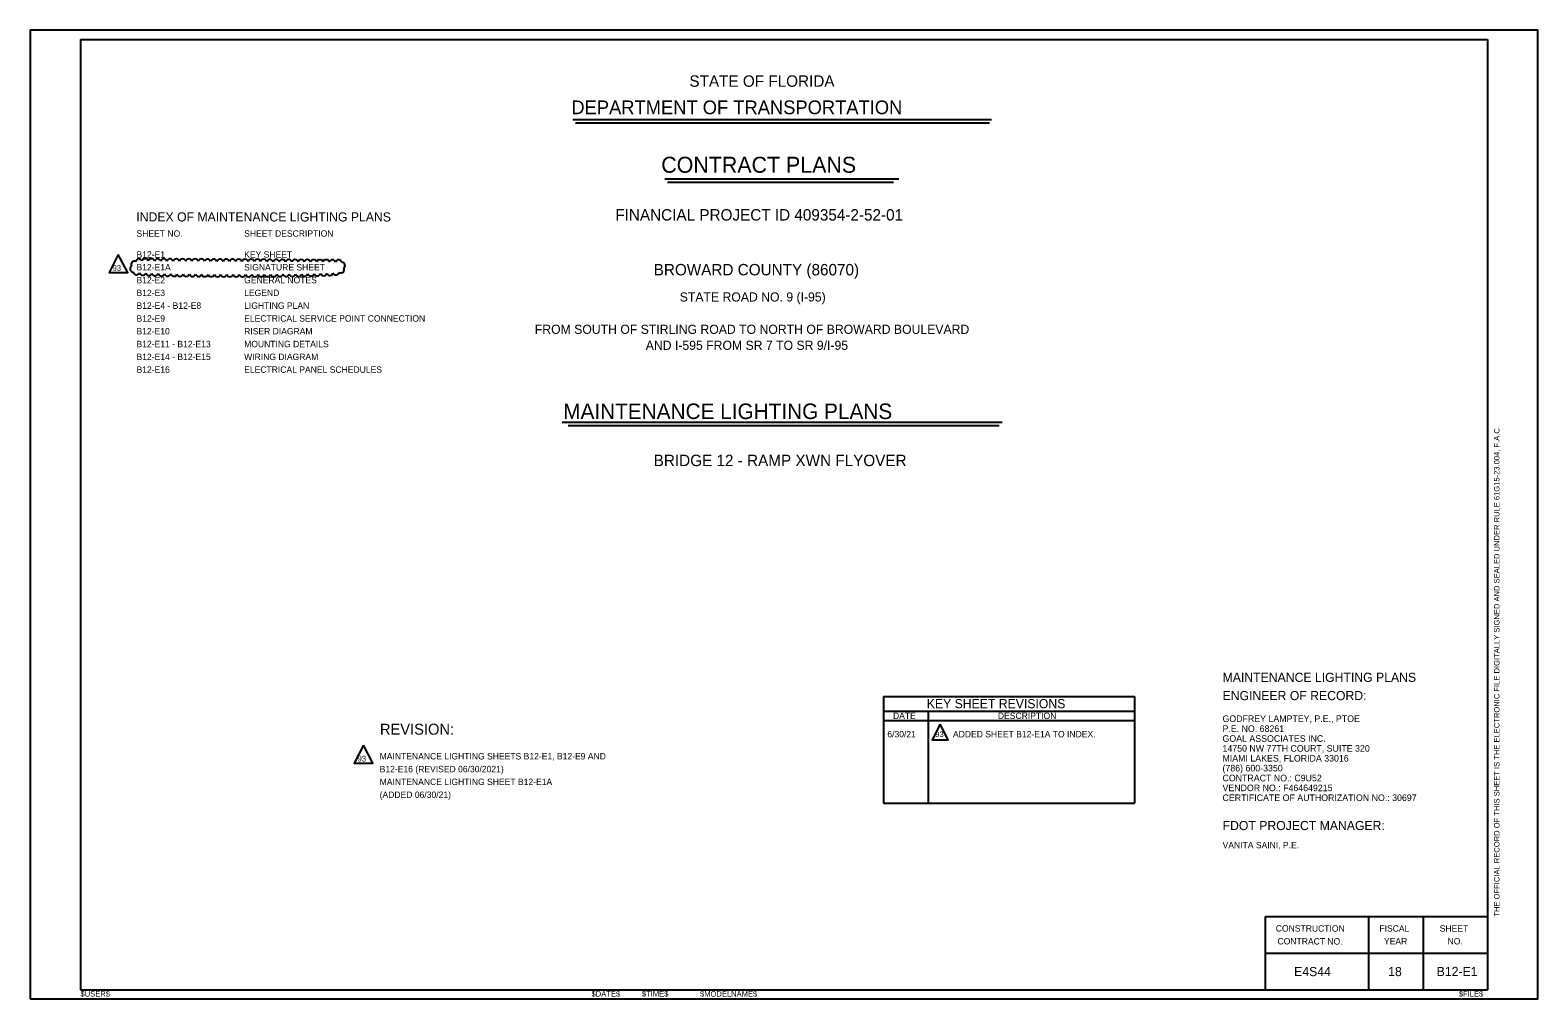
# Model space of a CAD drawing. Extents: x -820.2 to -803.7, y -2199.1 to -2188.5.
import ezdxf

# ---------------------------------------------------------------- set-up
doc = ezdxf.new("R2010")
doc.units = 0
for name, color, linetype in [('ActivePointCell_dp', 7, 'Continuous'), ('AdhocPoint_dp', 7, 'Continuous'), ('Cloud_dp', 7, 'Continuous'), ('PlotBorder_dp', 7, 'Continuous'), ('SheetBorder_dp', 7, 'Continuous'), ('SheetLines_dp', 7, 'Continuous'), ('SumBoxLines_dp', 7, 'Continuous'), ('TextLabel', 7, 'Continuous'), ('TextMinor', 7, 'Continuous'), ('TextMisc', 7, 'Continuous'), ('TextNotes', 7, 'Continuous'), ('TextTitle', 7, 'Continuous')]:
    doc.layers.add(name, color=color, linetype=linetype)

msp = doc.modelspace()

# ---------------------------------------------------------------- linework, layer by layer
at = {"layer": 'ActivePointCell_dp'}
msp.add_line((-804.277, -2188.624), (-804.277, -2188.624), dxfattribs=at)
at = {"layer": 'AdhocPoint_dp'}
msp.add_line((-803.727, -2199.124), (-803.727, -2199.124), dxfattribs=at)
at = {"layer": 'Cloud_dp'}
for points in [[(-819.262, -2190.977), (-819.364, -2191.174), (-819.159, -2191.174)], [(-810.268, -2196.119), (-810.356, -2196.288), (-810.18, -2196.288)]]:
    msp.add_lwpolyline(points, close=True, dxfattribs=at)
for centre, start, end in [((-819.036, -2191.063), 23.0939, 168.0939), ((-818.969, -2191.06), 17.1666, 162.1666), ((-818.901, -2191.06), 17.1666, 162.1666), ((-818.832, -2191.061), 17.1666, 162.1666), ((-818.764, -2191.061), 17.1666, 162.1666), ((-818.696, -2191.061), 17.1666, 162.1666), ((-818.627, -2191.062), 17.1666, 162.1666), ((-818.559, -2191.062), 17.1666, 162.1666), ((-818.491, -2191.063), 17.1666, 162.1666), ((-818.422, -2191.063), 17.1666, 162.1666), ((-818.354, -2191.063), 17.1666, 162.1666), ((-818.286, -2191.064), 17.1666, 162.1666), ((-818.217, -2191.064), 17.1666, 162.1666), ((-818.149, -2191.065), 17.1666, 162.1666), ((-818.081, -2191.065), 17.1666, 162.1666), ((-818.012, -2191.065), 17.1666, 162.1666), ((-817.944, -2191.066), 17.1667, 162.1667), ((-817.876, -2191.066), 17.1673, 162.1673), ((-817.808, -2191.067), 17.1678, 162.1678), ((-817.739, -2191.067), 17.1685, 162.1685), ((-817.671, -2191.067), 17.1692, 162.1692), ((-817.603, -2191.068), 17.17, 162.17), ((-817.534, -2191.068), 17.1709, 162.1709), ((-817.466, -2191.069), 17.172, 162.172), ((-817.398, -2191.069), 17.1733, 162.1733), ((-817.329, -2191.069), 17.1748, 162.1748), ((-817.261, -2191.07), 17.1767, 162.1767), ((-817.193, -2191.07), 17.1791, 162.1791), ((-817.124, -2191.071), 17.1823, 162.1823), ((-819.098, -2191.134), 124.4418, 269.4418), ((-819.087, -2191.088), 63.3859, 208.3859), ((-819.063, -2191.164), 190.134, 335.134), ((-818.996, -2191.17), 193.8651, 338.8651), ((-818.928, -2191.174), 194.9982, 339.9982), ((-818.86, -2191.176), 195.6143, 340.6143), ((-818.792, -2191.178), 196.0167, 341.0167), ((-818.723, -2191.18), 196.3062, 341.3062), ((-818.655, -2191.181), 196.5273, 341.5273), ((-818.587, -2191.182), 196.7034, 341.7034), ((-818.519, -2191.183), 196.8479, 341.8479), ((-818.45, -2191.184), 196.9693, 341.9693), ((-818.382, -2191.184), 197.0731, 342.0731), ((-818.314, -2191.185), 197.1633, 342.1633), ((-818.245, -2191.185), 197.2425, 342.2425), ((-818.177, -2191.186), 197.3128, 342.3128), ((-818.109, -2191.186), 197.3758, 342.3758), ((-818.041, -2191.186), 197.4327, 342.4327), ((-817.972, -2191.186), 197.4844, 342.4844), ((-817.904, -2191.186), 197.5356, 342.5356), ((-817.836, -2191.186), 197.5918, 342.5918), ((-817.767, -2191.186), 197.6538, 342.6538), ((-817.699, -2191.185), 197.7228, 342.7228), ((-817.631, -2191.185), 197.8002, 342.8002), ((-817.562, -2191.185), 197.8878, 342.8878), ((-817.494, -2191.184), 197.9881, 342.9881), ((-817.426, -2191.184), 198.1044, 343.1044), ((-817.358, -2191.183), 198.2416, 343.2416), ((-817.289, -2191.182), 198.4068, 343.4068), ((-817.221, -2191.181), 198.611, 343.611), ((-817.153, -2191.179), 198.8725, 343.8725), ((-817.085, -2191.177), 199.2244, 344.2244), ((-817.056, -2191.071), 17.187, 162.187), ((-817.016, -2191.175), 199.7353, 344.7353), ((-816.988, -2191.071), 17.1948, 162.1948), ((-816.948, -2191.172), 200.5799, 345.5799), ((-816.919, -2191.072), 17.2118, 162.2118), ((-816.88, -2191.167), 202.4501, 347.4501), ((-816.852, -2191.073), 14.8094, 159.8094), ((-816.827, -2191.144), 239.6728, 24.6728), ((-816.816, -2191.1), 306.3283, 91.3283)]:
    msp.add_arc(centre, 0.0358, start, end, dxfattribs=at)
at = {"layer": 'PlotBorder_dp'}
msp.add_lwpolyline([(-820.227, -2199.124), (-803.727, -2199.124), (-803.727, -2188.524), (-820.227, -2188.524)], close=True, dxfattribs=at)
at = {"layer": 'SheetBorder_dp'}
for p, q in [((-819.677, -2188.624), (-819.677, -2199.024)), ((-819.677, -2188.624), (-804.277, -2188.624)), ((-804.277, -2188.624), (-804.277, -2199.024)), ((-819.677, -2199.024), (-804.277, -2199.024))]:
    msp.add_line(p, q, dxfattribs=at)
at = {"layer": 'SheetLines_dp'}
for p, q in [((-806.708, -2198.224), (-804.277, -2198.224)), ((-806.708, -2199.024), (-806.708, -2198.224)), ((-805.577, -2199.024), (-805.577, -2198.224)), ((-804.977, -2199.024), (-804.977, -2198.224)), ((-806.708, -2198.624), (-804.277, -2198.624))]:
    msp.add_line(p, q, dxfattribs=at)
at = {"layer": 'SumBoxLines_dp'}
for p, q in [((-810.888, -2195.816), (-810.888, -2196.984)), ((-810.888, -2195.816), (-808.141, -2195.816)), ((-808.141, -2195.816), (-808.141, -2196.984)), ((-810.888, -2195.976), (-808.141, -2195.976)), ((-810.398, -2195.976), (-810.398, -2196.984)), ((-810.888, -2196.076), (-808.141, -2196.076)), ((-810.888, -2196.984), (-808.141, -2196.984))]:
    msp.add_line(p, q, dxfattribs=at)
at = {"layer": 'TextNotes'}
msp.add_lwpolyline([(-816.579, -2196.346), (-816.681, -2196.543), (-816.476, -2196.543)], close=True, dxfattribs=at)
at = {"layer": 'TextTitle'}
for p, q in [((-814.289, -2189.5), (-809.707, -2189.5)), ((-814.257, -2189.538), (-809.729, -2189.538)), ((-813.281, -2190.15), (-810.719, -2190.15)), ((-813.253, -2190.188), (-810.777, -2190.188)), ((-814.404, -2192.813), (-809.59, -2192.813)), ((-814.339, -2192.851), (-809.624, -2192.851))]:
    msp.add_line(p, q, dxfattribs=at)

# ---------------------------------------------------------------- texts
at = {"layer": 'Cloud_dp'}
for height, p in [(0.0622, (-819.325, -2191.157)), (0.06, (-810.322, -2196.258))]:
    msp.add_text('93', height=height, rotation=0, dxfattribs=at).set_placement(p)
at = {"layer": 'TextLabel'}
for s, height, p in [('INDEX OF MAINTENANCE LIGHTING PLANS', 0.1, (-819.065, -2190.617)), ('FINANCIAL PROJECT ID 409354-2-52-01', 0.125, (-813.823, -2190.607)), ('B12-E1', 0.07, (-819.063, -2191.013)), ('KEY SHEET', 0.07, (-817.885, -2191.013)), ('B12-E1A', 0.07, (-819.063, -2191.153)), ('SIGNATURE SHEET', 0.07, (-817.885, -2191.153)), ('BROWARD COUNTY (86070)', 0.125, (-813.403, -2191.207)), ('B12-E2', 0.07, (-819.063, -2191.293)), ('B12-E3', 0.07, (-819.063, -2191.433)), ('GENERAL NOTES', 0.07, (-817.885, -2191.293)), ('LEGEND', 0.07, (-817.885, -2191.433)), ('B12-E4 - B12-E8', 0.07, (-819.063, -2191.573)), ('LIGHTING PLAN', 0.07, (-817.885, -2191.573)), ('STATE ROAD NO. 9 (I-95)', 0.1, (-813.118, -2191.493)), ('B12-E9', 0.07, (-819.063, -2191.713)), ('ELECTRICAL SERVICE POINT CONNECTION', 0.07, (-817.885, -2191.713)), ('B12-E10', 0.07, (-819.063, -2191.853)), ('RISER DIAGRAM', 0.07, (-817.885, -2191.853)), ('FROM SOUTH OF STIRLING ROAD TO NORTH OF BROWARD BOULEVARD', 0.1, (-814.704, -2191.847)), ('B12-E11 - B12-E13', 0.07, (-819.063, -2191.993)), ('MOUNTING DETAILS', 0.07, (-817.885, -2191.993)), ('AND I-595 FROM SR 7 TO SR 9/I-95', 0.1, (-813.49, -2192.022)), ('B12-E14 - B12-E15', 0.07, (-819.063, -2192.133)), ('WIRING DIAGRAM', 0.07, (-817.885, -2192.133)), ('B12-E16', 0.07, (-819.063, -2192.273)), ('ELECTRICAL PANEL SCHEDULES', 0.07, (-817.885, -2192.273)), ('BRIDGE 12 - RAMP XWN FLYOVER', 0.125, (-813.403, -2193.294)), ('MAINTENANCE LIGHTING PLANS', 0.1, (-807.177, -2195.655)), ('ENGINEER OF RECORD:', 0.1, (-807.177, -2195.855)), ('KEY SHEET REVISIONS', 0.1, (-810.414, -2195.943)), ('REVISION:', 0.12, (-816.399, -2196.233)), ('GODFREY LAMPTEY, P.E., PTOE', 0.07202, (-807.178, -2196.094)), ('P.E. NO. 68261', 0.07202, (-807.178, -2196.203)), ('GOAL ASSOCIATES INC. ', 0.07202, (-807.178, -2196.311)), ('14750 NW 77TH COURT, SUITE 320', 0.07202, (-807.178, -2196.419)), ('MIAMI LAKES, FLORIDA 33016', 0.07202, (-807.178, -2196.527)), ('(786) 600-3350', 0.07202, (-807.178, -2196.635)), ('VENDOR NO.: F464649215', 0.07202, (-807.178, -2196.851)), ('CONTRACT NO.: C9U52', 0.07202, (-807.178, -2196.743)), ('CERTIFICATE OF AUTHORIZATION NO.: 30697', 0.07202, (-807.178, -2196.959)), ('E4S44', 0.1, (-806.394, -2198.875)), ('18', 0.1, (-805.365, -2198.875)), ('B12-E1', 0.1, (-804.834, -2198.874))]:
    msp.add_text(s, height=height, dxfattribs=at).set_placement(p)
at = {"layer": 'TextMinor'}
for s, height, p in [('6/30/21', 0.07, (-810.846, -2196.262)), ('ADDED SHEET B12-E1A TO INDEX.', 0.07, (-810.128, -2196.262)), ('$FILE$', 0.06, (-804.592, -2199.099))]:
    msp.add_text(s, height=height, dxfattribs=at).set_placement(p)
for s, p in [('$USER$', (-819.676, -2199.099)), ('$DATE$', (-814.083, -2199.099)), ('$TIME$', (-813.532, -2199.099)), ('$MODELNAME$', (-812.896, -2199.099))]:
    msp.add_text(s, height=0.06, rotation=360, dxfattribs=at).set_placement(p)
at = {"layer": 'TextMisc'}
msp.add_text('THE OFFICIAL RECORD OF THIS SHEET IS THE ELECTRONIC FILE DIGITALLY SIGNED AND SEALED UNDER RULE 61G15-23.004, F.A.C.', height=0.06, rotation=90, dxfattribs=at).set_placement((-804.147, -2198.224))
at = {"layer": 'TextNotes'}
for s, height, p in [('SHEET NO.', 0.07, (-819.063, -2190.784)), ('SHEET DESCRIPTION', 0.07, (-817.885, -2190.784)), ('DATE', 0.07, (-810.784, -2196.061)), ('DESCRIPTION', 0.07, (-809.636, -2196.061)), ('MAINTENANCE LIGHTING SHEETS B12-E1, B12-E9 AND ', 0.07, (-816.402, -2196.504)), ('B12-E16 (REVISED 06/30/2021)', 0.07, (-816.402, -2196.644)), ('MAINTENANCE LIGHTING SHEET B12-E1A ', 0.07, (-816.402, -2196.784)), ('(ADDED 06/30/21)', 0.07, (-816.402, -2196.925)), ('FDOT PROJECT MANAGER:', 0.1, (-807.177, -2197.277)), ('VANITA SAINI, P.E.', 0.07, (-807.177, -2197.476))]:
    msp.add_text(s, height=height, dxfattribs=at).set_placement(p)
for s, height, rotation, p in [('93', 0.0622, 0, (-816.643, -2196.526)), ('CONSTRUCTION', 0.07, 359.8607, (-806.595, -2198.387)), ('CONTRACT NO.', 0.07, 359.8607, (-806.576, -2198.528)), ('FISCAL', 0.07, 359.8607, (-805.461, -2198.388)), ('YEAR', 0.07, 359.8607, (-805.411, -2198.528)), ('SHEET', 0.07, 359.8607, (-804.801, -2198.388)), ('NO.', 0.07, 359.8607, (-804.715, -2198.528))]:
    msp.add_text(s, height=height, rotation=rotation, dxfattribs=at).set_placement(p)
at = {"layer": 'TextTitle'}
for s, height, p in [('STATE OF FLORIDA', 0.125, (-813.012, -2189.143)), ('DEPARTMENT OF TRANSPORTATION', 0.15, (-814.304, -2189.443)), ('CONTRACT PLANS', 0.175, (-813.32, -2190.084)), ('MAINTENANCE LIGHTING PLANS', 0.17, (-814.393, -2192.779))]:
    msp.add_text(s, height=height, dxfattribs=at).set_placement(p)

doc.saveas('drawing.dxf')
